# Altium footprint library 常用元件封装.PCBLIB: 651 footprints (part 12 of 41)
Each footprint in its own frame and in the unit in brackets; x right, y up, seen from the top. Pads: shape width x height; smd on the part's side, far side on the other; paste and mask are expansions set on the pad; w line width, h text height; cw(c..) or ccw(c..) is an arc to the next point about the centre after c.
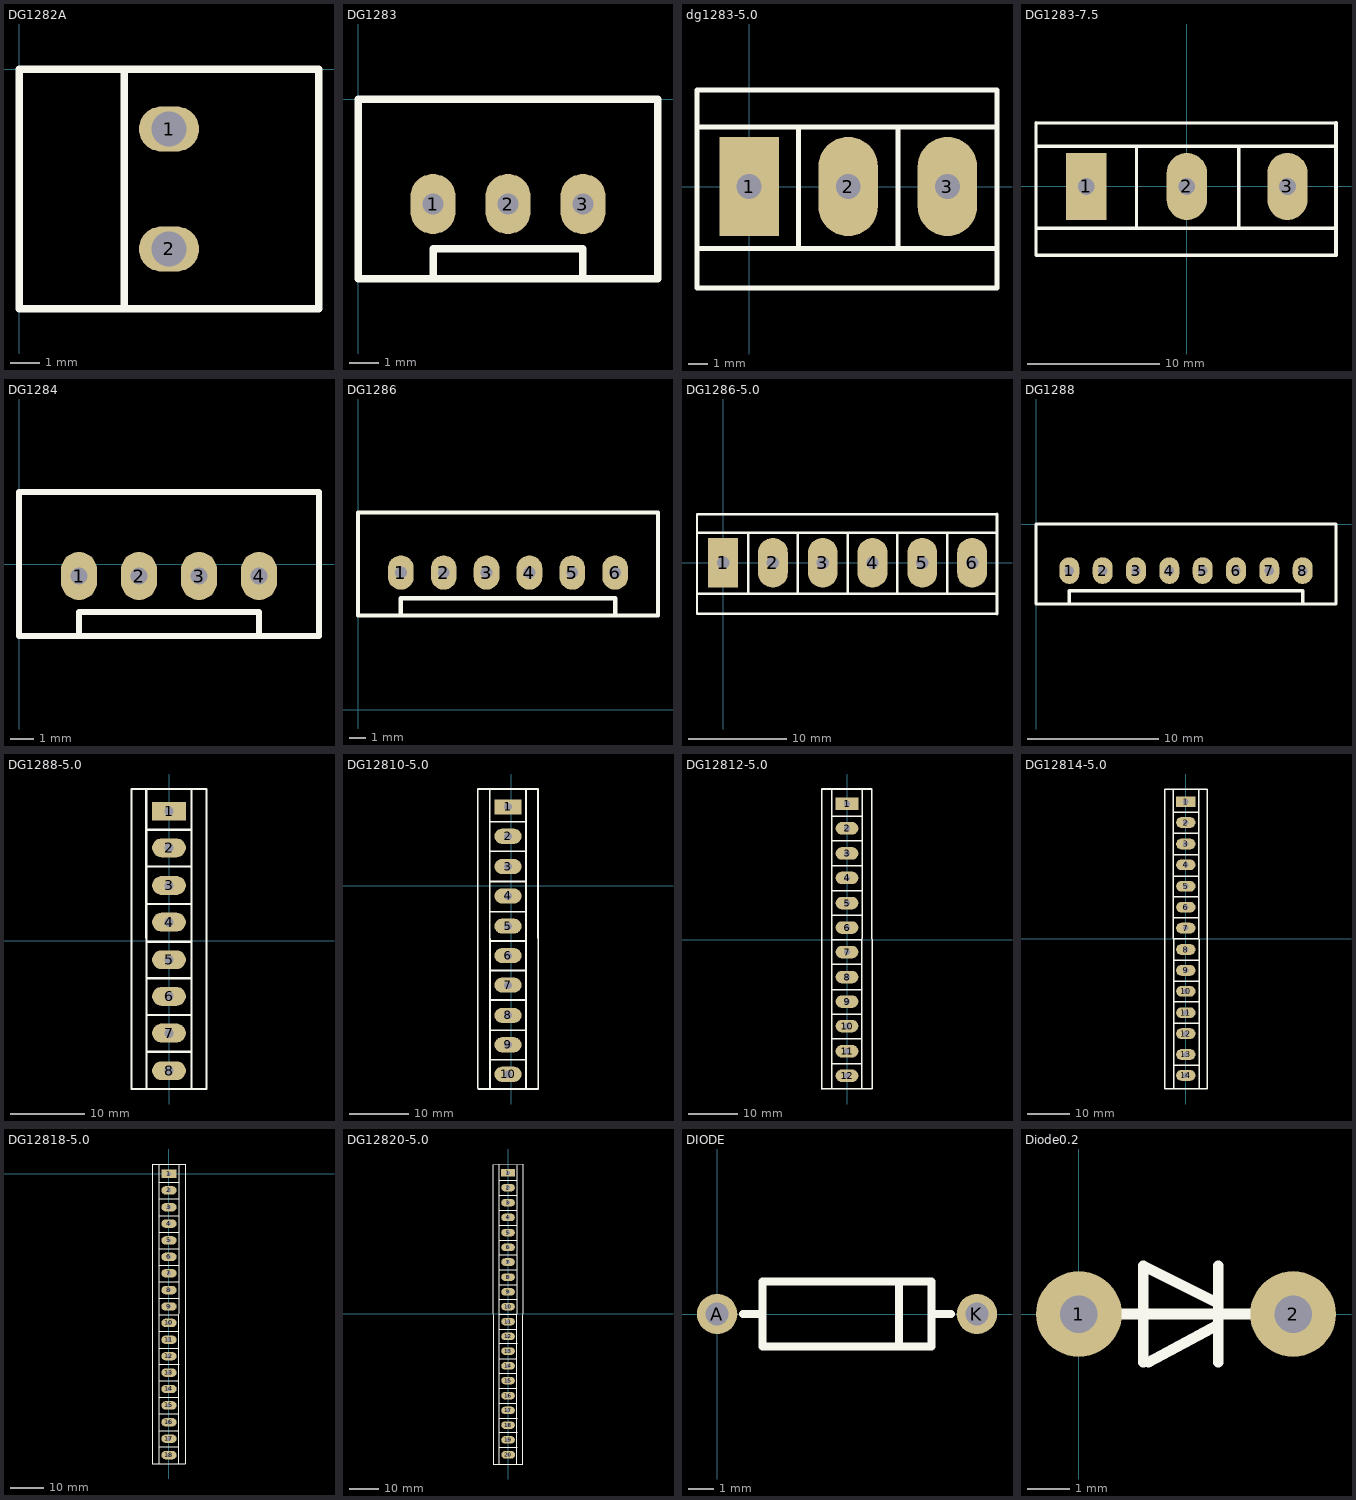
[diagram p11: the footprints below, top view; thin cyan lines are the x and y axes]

## DG1282A [mil]
pads (2):
  oval 80x60 hole 47.24: 1(200,-80) 2(200,-240)
TopOverlay:
  lines w10: 140,-320 140,0 ; 0,-320 0,-20 0,0 240,0 260,0 280,0 360,0 400,0 400,-320 360,-320 280,-320 260,-320 240,-320 0,-320

## DG1283 [mil]
pads (3):
  oval 60x80 hole 27.56: 1(100,-140) 2(200,-140) 3(300,-140)
TopOverlay:
  lines w10: 100,-240 100,-200 300,-200 300,-240 ; 0,-240 0,-120 0,0 400,0 400,-240 0,-240

## dg1283-5.0 [mil]
pads (3):
  rect 120x200 hole 50: 1(0,0)
  oval 120x200 hole 50: 2(200,0) 3(400,0)
TopOverlay:
  lines w10: -105,-203 -105,-205 500,-205 500,195 -105,195 ; -105,-200 -105,191 ; -105,-125 500,-125 ; -105,120 500,120 ; 100,-124 100,120 ; 300,-125 300,120

## DG1283-7.5 [mil]
pads (3):
  rect 120x200 hole 50: 1(-300,0)
  oval 120x200 hole 50: 2(0,0) 3(300,0)
TopOverlay:
  lines w10: -450,-125 445,-125 ; -450,120 445,120 ; -450,186 -450,-205 445,-205 ; -450,190 445,189 ; -150,-124 -150,120 ; 155,-125 155,120
  lines w12: 445,-205 445,189

## DG1284 [mil]
pads (4):
  oval 60x80 hole 27.56: 1(100,-20) 2(200,-20) 3(300,-20) 4(400,-20)
TopOverlay:
  lines w10: 100,-120 100,-80 400,-80 400,-120 ; 0,-120 480,-120 500,-120 500,120 0,120 0,0 0,-120

## DG1286 [mil]
pads (6):
  oval 60x80 hole 27.56: 1(100,320) 2(200,320) 3(300,320) 4(400,320) 5(500,320) 6(600,320)
TopOverlay:
  lines w10: 100,220 100,260 400,260 600,260 600,220 ; 0,220 480,220 500,220 700,220 700,460 500,460 0,460 0,340 0,220

## DG1286-5.0 [mil]
pads (6):
  rect 120x200 hole 50: 1(0,0)
  oval 120x200 hole 50: 2(200,0) 3(400,0) 4(600,0) 5(800,0) 6(1000,0)
TopOverlay:
  lines w10: -105,-203 -105,-205 1100,-205 ; -105,-200 -105,191 ; -105,-125 1100,-125 ; -105,120 1100,120 ; -105,195 1095,195 ; 100,-124 100,120 ; 300,-125 300,120 ; 500,-125 500,120 ; 700,-125 700,120 ; 900,-125 900,120
  lines w12: 1100,-205 1100,195

## DG1288 [mil]
pads (8):
  oval 60x80 hole 27.56: 1(100,-140) 2(200,-140) 3(300,-140) 4(400,-140) 5(500,-140) 6(600,-140) 7(700,-140) 8(800,-140)
TopOverlay:
  lines w10: 100,-240 100,-200 400,-200 600,-200 800,-200 800,-240 ; 0,-240 0,-120 0,0 500,0 700,0 900,0 900,-240 700,-240 500,-240 480,-240 0,-240

## DG1288-5.0 [mil]
pads (8):
  rect 180x100 hole 50: 1(0,690)
  oval 180x100 hole 50: 2(0,495) 3(0,295) 4(0,100) 5(0,-100) 6(0,-295) 7(0,-490) 8(0,-690)
TopOverlay:
  lines w12: -121,808 -120,-782.5 ; -117,591 118,591 ; -112,-589 118,-589 ; -112,-394 118,-394 ; -112,-199 118,-199 ; -112,-4 118,-4 ; -112,196 118,196 ; -112,396 118,396 ; 120,-787.5 120,808 ; 199,-787.5 -200,-787.5 -200,808 199,808 200,-787.5

## DG12810-5.0 [mil]
pads (10):
  rect 180x100 hole 50: 1(-20,522.5)
  oval 180x100 hole 50: 2(-20,327.5) 3(-20,127.5) 4(-20,-67.5) 5(-20,-267.5) 6(-20,-462.5) 7(-20,-657.5) 8(-20,-857.5) 9(-20,-1052.5) 10(-20,-1247.5)
TopOverlay:
  lines w12: -220,-1340 -220,640.5 179,640.5 180,-1340 ; -215,-1345 179,-1345 ; -141,640.5 -140,-1340 ; -137,423.5 98,423.5 ; -132,-1151.5 98,-1151.5 ; -132,-956.5 98,-956.5 ; -132,-756.5 98,-756.5 ; -132,-561.5 98,-561.5 ; -132,-366.5 98,-366.5 ; -132,-171.5 98,-171.5 ; -132,28.5 98,28.5 ; -132,228.5 98,228.5 ; 100,-1340 100,640.5

## DG12812-5.0 [mil]
pads (12):
  rect 180x100 hole 50: 1(0,1082.5)
  oval 180x100 hole 50: 2(0,887.5) 3(0,687.5) 4(0,492.5) 5(0,292.5) 6(0,97.5) 7(0,-97.5) 8(0,-297.5) 9(0,-492.5) 10(0,-687.5) 11(0,-887.5) 12(0,-1082.5)
TopOverlay:
  lines w12: -200,-1188 -200,1200.5 199,1200.5 200,-1185 ; -195,-1185 199,-1185 ; -123,-1185 -121,1200.5 ; -117,983.5 118,983.5 ; -112,-986.5 118,-986.5 ; -112,-786.5 118,-786.5 ; -112,-591.5 118,-591.5 ; -112,-396.5 118,-396.5 ; -112,-196.5 118,-196.5 ; -112,-1.5 118,-1.5 ; -112,193.5 118,193.5 ; -112,388.5 118,388.5 ; -112,588.5 118,588.5 ; -112,788.5 118,788.5 ; 117,-1182 120,1200.5

## DG12814-5.0 [mil]
pads (14):
  rect 180x100 hole 50: 1(0,1277.5)
  oval 180x100 hole 50: 2(0,1082.5) 3(0,882.5) 4(0,687.5) 5(0,487.5) 6(0,292.5) 7(0,97.5) 8(0,-102.5) 9(0,-297.5) 10(0,-492.5) 11(0,-692.5) 12(0,-887.5) 13(0,-1082.5) 14(0,-1277.5)
TopOverlay:
  lines w12: -117,1178.5 118,1178.5 ; -116,1395.5 -111,-1404.5 ; -112,-1181.5 118,-1181.5 ; -112,-791.5 118,-791.5 ; -112,-591.5 118,-591.5 ; -112,-396.5 118,-396.5 ; -112,-201.5 118,-201.5 ; -112,-1.5 118,-1.5 ; -112,193.5 118,193.5 ; -112,388.5 118,388.5 ; -112,583.5 118,583.5 ; -112,783.5 118,783.5 ; -112,983.5 118,983.5 ; 120,1395.5 124,-1404.5 ; -195,-1404.5 -195,1395.5 199,1395.5 199,-1404.5 -195,-1404.5

## DG12818-5.0 [mil]
pads (18):
  rect 180x100 hole 50: 1(0,0)
  oval 180x100 hole 50: 2(0,-195) 3(0,-395) 4(0,-590) 5(0,-790) 6(0,-985) 7(0,-1180) 8(0,-1380) 9(0,-1575) 10(0,-1770) 11(0,-1970) 12(0,-2165) 13(0,-2360) 14(0,-2555) 15(0,-2750) 16(0,-2950) 17(0,-3145) 18(0,-3340)
TopOverlay:
  lines w10: -117,-2258.5 123,-2258.5 ; -115.5,-3243 116.5,-3243
  lines w12: -198.5,-3446 195.5,-3446 ; -197,-3446 -198.5,118 199,118 198,-3446 ; -117,-3446 -116,118 ; -117,-99 118,-99 ; -112,-3049 118,-3049 ; -112,-2849 118,-2849 ; -112,-2654 118,-2654 ; -112,-2459 118,-2459 ; -112,-2069 118,-2069 ; -112,-1869 118,-1869 ; -112,-1674 118,-1674 ; -112,-1479 118,-1479 ; -112,-1279 118,-1279 ; -112,-1084 118,-1084 ; -112,-889 118,-889 ; -112,-694 118,-694 ; -112,-494 118,-494 ; -112,-294 118,-294 ; 118,-3446 121,110.5

## DG12820-5.0 [mil]
pads (20):
  rect 180x100 hole 50: 1(-1.5,1866)
  oval 180x100 hole 50: 2(-1.5,1671) 3(-1.5,1471) 4(-1.5,1276) 5(-1.5,1076) 6(-1.5,881) 7(-1.5,686) 8(-1.5,486) 9(-1.5,291) 10(-1.5,96) 11(-1.5,-104) 12(-1.5,-299) 13(-1.5,-494) 14(-1.5,-689) 15(-1.5,-884) 16(-1.5,-1084) 17(-1.5,-1279) 18(-1.5,-1474) 19(-1.5,-1669) 20(1.5,-1866)
TopOverlay:
  lines w10: -121.5,-1379.5 118.5,-1379.5 ; -120.5,-1570.5 119.5,-1570.5 ; -118.5,-392.5 121.5,-392.5
  lines w12: -198.5,-1988.5 195.5,-1988.5 ; -198.5,-1988 -201.5,1976.5 197.5,1984 196.5,-1988.5 ; -118.5,-1988.5 -117.5,1984 ; -118.5,1767 116.5,1767 ; -113.5,-1183 116.5,-1183 ; -113.5,-983 116.5,-983 ; -113.5,-788 116.5,-788 ; -113.5,-593 116.5,-593 ; -113.5,-203 116.5,-203 ; -113.5,-3 116.5,-3 ; -113.5,192 116.5,192 ; -113.5,387 116.5,387 ; -113.5,587 116.5,587 ; -113.5,782 116.5,782 ; -113.5,977 116.5,977 ; -113.5,1172 116.5,1172 ; -113.5,1372 116.5,1372 ; -113.5,1572 116.5,1572 ; -110.5,-1770 119.5,-1770 ; 116.5,-1988.5 119.5,1976.5

## DIODE [mil]
pads (2):
  round 62 hole 35.43: A(0,0) K(400,0)
TopOverlay:
  lines w12: 40,0 70,0 ; 280,-50 280,50 ; 330,0 360,0 ; 70,-50 70,50 330,50 330,-50 70,-50

## Diode0.2 [mil]
pads (2):
  round 80 hole 35: 1(0,0) 2(200,0)
TopOverlay:
  lines w10: 35,0 160,0 ; 60,-45 60,45 130,10 ; 65,-45 130,-10 ; 130,-45 130,45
